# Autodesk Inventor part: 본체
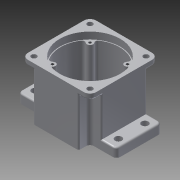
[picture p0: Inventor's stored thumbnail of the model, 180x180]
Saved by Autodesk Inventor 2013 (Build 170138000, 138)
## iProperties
Created: 2015-07
Part Number: 본체
Material: 알루미늄 6061
Document SubType Name: Modeling
Designer: user
Density: 2.71 g/cm^3
Mass: 705.035 g
Surface Area: 673.943 cm^2
Volume: 260.16 cm^3
Author: user
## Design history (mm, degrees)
sketch "스케치1"
  geometry: L1 (-45, 45)-(45, 45); L2 (45, 45)-(45, -45); L3 (45, -45)-(-45, -45); L4 (-45, -45)-(-45, 45); 3 further points
  constraints: 8 end point, 2 midpoint, 2 parallel, 1 horizontal, 1 horizontal alignment, 1 perpendicular, 1 vertical alignment
  dimensions: "d0" = 90 distance of L2.end L3.end; "d1" = 90 distance of L1.end L2.end
extrude "돌출1" new body sketch "스케치1" stored distance "d2" = 70; taper "d3" = 0 deg
sketch "스케치2"
  geometry: L1 (0, 90)-(70, 90) reference; L2 (0, 0)-(0, 90) reference; L3 (0, 0)-(70, 0) reference; L4 (70, 90)-(70, 0) reference; 1 further point
sketch "스케치3"
  geometry: L1 (-45, 45)-(-45, -45) reference; L2 (0, 0)-(65, 0); L3 (65, 0)-(65, 30); L4 (65, 30)-(-65, 30); L5 (-65, 30)-(-65, -30); L6 (-65, -30)-(65, -30); L7 (65, -30)-(65, 0)
  constraints: 12 end point, 3 perpendicular, 2 parallel
  dimensions: "d4" = 65 distance of L2.start L2.end; "d5" = 30 distance of L2.end L3.end; "d6" = 130 distance of L3.end L4.end; "d7" = 60 distance of L4.end L5.end; "d8" = 130 distance of L5.end L6.end
extrude "돌출2" join sketch "스케치3" distance "d9" = 12; taper "d10" = 0 deg
sketch "스케치4"
  geometry: L1 (-45, -45)-(45, -45) reference; L2 (45, -45)-(45, -30) reference; L3 (0, 0)-(0, -45); L4 (0, -45)-(30, -45); L5 (45, -30)-(22.936, -30); L6 (30, -45)-(30, -30); L7 (30, -45)-(45, -45)
  constraints: 10 end point, 2 point on line, 1 collinear, 1 midpoint, 1 parallel, 1 perpendicular
  dimensions: "d11" = 30 distance of L3.end L4.end
extrude "돌출3" cut sketch "스케치4" distance "d12" = 63; taper "d13" = 0 deg
fillet "모깎기1" dims "d14" = 8
fillet "모깎기2" dims "d15" = 5
sketch "스케치5"
  geometry: L1 (-65, 25)-(-65, -25) reference; L2 (0, 0)-(0, 11); C1 r 25 at (0, 11)
  constraints: 2 end point, 1 centre point, 1 coincident, 1 parallel
  dimensions: "d16" = 11 distance of L2.start L2.end; "d17" = 25 radius of C1
extrude "돌출4" join sketch "스케치5" distance "d18" = 7; taper "d19" = 0 deg
sketch "스케치6"
  geometry: C1 r 40 at (0, 0); 1 further point
  constraints: 1 centre point, 1 coincident
  dimensions: "d21" = 40 radius of C1
extrude "돌출5" cut sketch "스케치6" distance "d22" = 9; taper "d23" = 0 deg
sketch "스케치7"
  geometry: C1 r 40 at (0, 0) reference; C2 r 39 at (0, 0)
  constraints: 1 centre point, 1 coincident
  dimensions: "d24" = 39 radius of C2
extrude "돌출6" cut sketch "스케치7" distance "d25" = 52; taper "d26" = 0 deg
sketch "스케치8"
  geometry: L1 (0, 0)-(0, 11); L2 (0, 0)-(0, -20); C1 r 39 at (0, 0) reference; A1 r 20.5 centre (0, 11) between (7.402, -8.117) and (-7.402, -8.117); A2 r 14 centre (0, -20) between (-7.402, -8.117) and (7.402, -8.117)
  constraints: 4 end point, 4 point on circle, 2 centre point, 2 coincident, 1 collinear, 1 vertical
  dimensions: "d27" = 11 distance of L1.start L1.end; "d28" = 20.5 radius of A1; "d29" = 20 distance of L1.start L2.end; "d30" = 14 radius of A2
extrude "돌출7" join sketch "스케치8" distance "d31" = 7; taper "d32" = 0 deg
sketch "스케치9"
  geometry: C1 r 25 at (0, 0) reference; C2 r 16 at (0, 0); 1 further point
  constraints: 1 centre point, 1 coincident
  dimensions: "d33" = 16 radius of C2
extrude "돌출8" cut sketch "스케치9" distance "d34" = 8; taper "d35" = 0 deg
sketch "스케치10"
  geometry: C1 r 16 at (0, 0) reference; C2 r 12.5 at (0, 0); 1 further point
  constraints: 1 centre point, 1 coincident
  dimensions: "d36" = 12.5 radius of C2
extrude "돌출9" cut sketch "스케치10" distance "d37" = 5; taper "d38" = 0 deg
sketch "스케치11"
  geometry: C1 r 12.5 at (0, 0) reference; C2 r 17.5 at (0, 0); 1 further point
  constraints: 1 centre point, 1 coincident
  dimensions: "d39" = 17.5 radius of C2
extrude "돌출10" cut sketch "스케치11" distance "d40" = 10; taper "d41" = 0 deg
sketch "스케치12"
  geometry: C1 r 11 at (0, -20); A1 r 14 centre (0, -20) between (-7.402, -8.117) and (7.402, -8.117) reference; 1 further point
  constraints: 1 centre point, 1 coincident
  dimensions: "d42" = 11 radius of C1
extrude "돌출11" cut sketch "스케치12" distance "d43" = 7; taper "d44" = 0 deg
sketch "스케치13"
  geometry: C1 r 11 at (0, 0) reference; C2 r 9.5 at (0, 0); 1 further point
  constraints: 1 centre point, 1 coincident
  dimensions: "d45" = 9.5 radius of C2
extrude "돌출12" cut sketch "스케치13" distance "d46" = 1; taper "d47" = 0 deg
fillet "모깎기3" dims "d48" = 5
sketch "스케치14"
  geometry: L1 (0, 0)-(24.749, 24.749); L2 (0, 0)-(35, 0); L3 (0, 0)-(0, 19.238); L4 (0, 0)-(-8.999, 0); A1 r 39 centre (0, 0) between (32.777, 21.134) and (21.134, 32.777) reference; A2 r 4 centre (24.749, 24.749) between (21.809, 27.462) and (27.462, 21.809); A3 r 3.5 centre (29.836, 19.238) between (32.777, 21.134) and (27.412, 21.762); A4 r 3.5 centre (19.238, 29.836) between (21.762, 27.412) and (21.134, 32.777); A5 r 3.5 centre (-19.238, 29.836) between (-21.134, 32.777) and (-21.762, 27.412); A6 r 4 centre (-24.749, 24.749) between (-27.462, 21.809) and (-21.809, 27.462); A7 r 3.5 centre (-29.836, 19.238) between (-27.412, 21.762) and (-32.777, 21.134); A8 r 3.5 centre (-19.238, -29.836) between (-21.762, -27.412) and (-21.134, -32.777); A9 r 4 centre (-24.749, -24.749) between (-21.809, -27.462) and (-27.462, -21.809); A10 r 3.5 centre (-29.836, -19.238) between (-32.777, -21.134) and (-27.412, -21.762); A11 r 4 centre (24.749, -24.749) between (27.462, -21.809) and (21.809, -27.462); A12 r 3.5 centre (29.836, -19.238) between (27.412, -21.762) and (32.777, -21.134); A13 r 3.5 centre (19.238, -29.836) between (21.134, -32.777) and (21.762, -27.412); A14 r 39 centre (0, 0) between (-32.777, -21.134) and (-21.134, -32.777); A15 r 39 centre (0, 0) between (21.134, -32.777) and (32.777, -21.134); A16 r 39 centre (0, 0) between (32.777, 21.134) and (21.134, 32.777); A17 r 39 centre (0, 0) between (-21.134, 32.777) and (-32.777, 21.134)
  constraints: 42 point on circle, 27 symmetric about line, 16 centre point, 8 end point, 4 tangent, 3 coincident, 2 perpendicular, 1 equal length, 1 horizontal, 9 other
  dimensions: "d50" = 45 deg angle of L2 L1; "d56" = 4 radius of A2; "d57" = 3.5 radius of A3; "d58" = 3.5 radius of A4
extrude "돌출13" join sketch "스케치14" distance "d59" = 52; taper "d60" = 0 deg
fillet "모깎기4" dims "d61" = 3
fillet "모깎기5" dims "d62" = 2
chamfer "모따기1" distance "d64" = 1; stored, may be unused: second distance "d65" = 2, angle "d66" = 45 deg
fillet "모깎기7" dims "d67" = 0.3
fillet "모깎기8" dims "d68" = 0.3
fillet "모깎기9" dims "d69" = 0.3
chamfer "모따기2" distance "d70" = 1; stored, may be unused: second distance "d71" = 2, angle "d72" = 45 deg
fillet "모깎기10" dims "d73" = 2
fillet "모깎기11" dims "d74" = 2
fillet "모깎기12" dims "d75" = 2
sketch "스케치15"
  geometry: L1 (0, -7)-(0, 0) reference; L2 (43, 30)-(43, 10.278); L3 (43, 30)-(26.669, 30); C1 r 3.5 at (6, -7); C2 r 3.5 at (80, -7); C3 r 3.5 at (6, 67); C4 r 3.5 at (80, 67); A1 r 6 centre (6, -7) between (0, -7) and (6, -13) reference
  constraints: 4 centre point, 4 end point, 3 symmetric about line, 1 coincident, 1 parallel, 1 perpendicular, 3 other
  dimensions: "d76" = 3.5 radius of C1
extrude "돌출14" cut sketch "스케치15" distance "d77" = 61; taper "d78" = 0 deg
sketch "스케치16"
  geometry: L1 (-30, -35)-(-30, -43) reference; L2 (0, 0)-(55, 0); L3 (55, 0)-(55, 17.5); L4 (0, 0)-(0, 15.913); C1 r 4.5 at (55, 17.5); C2 r 4.5 at (55, -17.5); C3 r 4.5 at (-55, 17.5); C4 r 4.5 at (-55, -17.5)
  constraints: 6 end point, 4 centre point, 3 symmetric about line, 2 perpendicular, 1 coincident, 1 parallel, 3 other
  dimensions: "d79" = 55 distance of L2.start L2.end; "d80" = 17.5 distance of L2.end L3.end; "d81" = 4.5 radius of C1
extrude "돌출15" cut sketch "스케치16" distance "d82" = 61; taper "d83" = 0 deg
sketch "스케치17"
  geometry: L1 (-28, -45)-(28, -45) reference; L2 (-30, -35)-(-30, -43) reference; L3 (0, -45)-(0, -30); 2 further points
  constraints: 2 end point, 1 coincident, 1 midpoint, 1 parallel, 1 other
  dimensions: "d85" = 15 distance of L3.start L3.end
extrude "돌출16" join sketch "스케치17" distance "d86" = 0.5; taper "d87" = 0 deg
fillet "모깎기13" dims "d88" = 2
fillet "모깎기14" dims "d89" = 2
fillet "모깎기15" dims "d90" = 2
sketch "스케치18"
  geometry: A1 r 4 centre (24.749, 24.749) between (21.809, 27.462) and (27.462, 21.809) reference
hole "구멍1" sketch "스케치18" at (24.749, 24.749) diameter "d92" = 3.459; stored, may be unused: countersink angle "d96" = 90 deg, drill point angle "d98" = 118 deg; dims "d93" = 12, "d94" = 4, "d95" = 2, "d97" = 15
chamfer "모따기3" distance "d102" = 1; stored, may be unused: second distance "d103" = 2, angle "d104" = 45 deg
chamfer "모따기4" distance "d105" = 1; stored, may be unused: second distance "d106" = 2, angle "d107" = 45 deg
node "솔리드1"
mirror "대칭1"
mirror "대칭2"
mirror "대칭3"
mirror "대칭4"
mirror "대칭5"
mirror "대칭6"
mirror "대칭7"
mirror "대칭8"
mirror "대칭9"
pattern_circular "원형 패턴1" dims angle "d100" = 360 deg
other parameters: "d55" = 3.5
